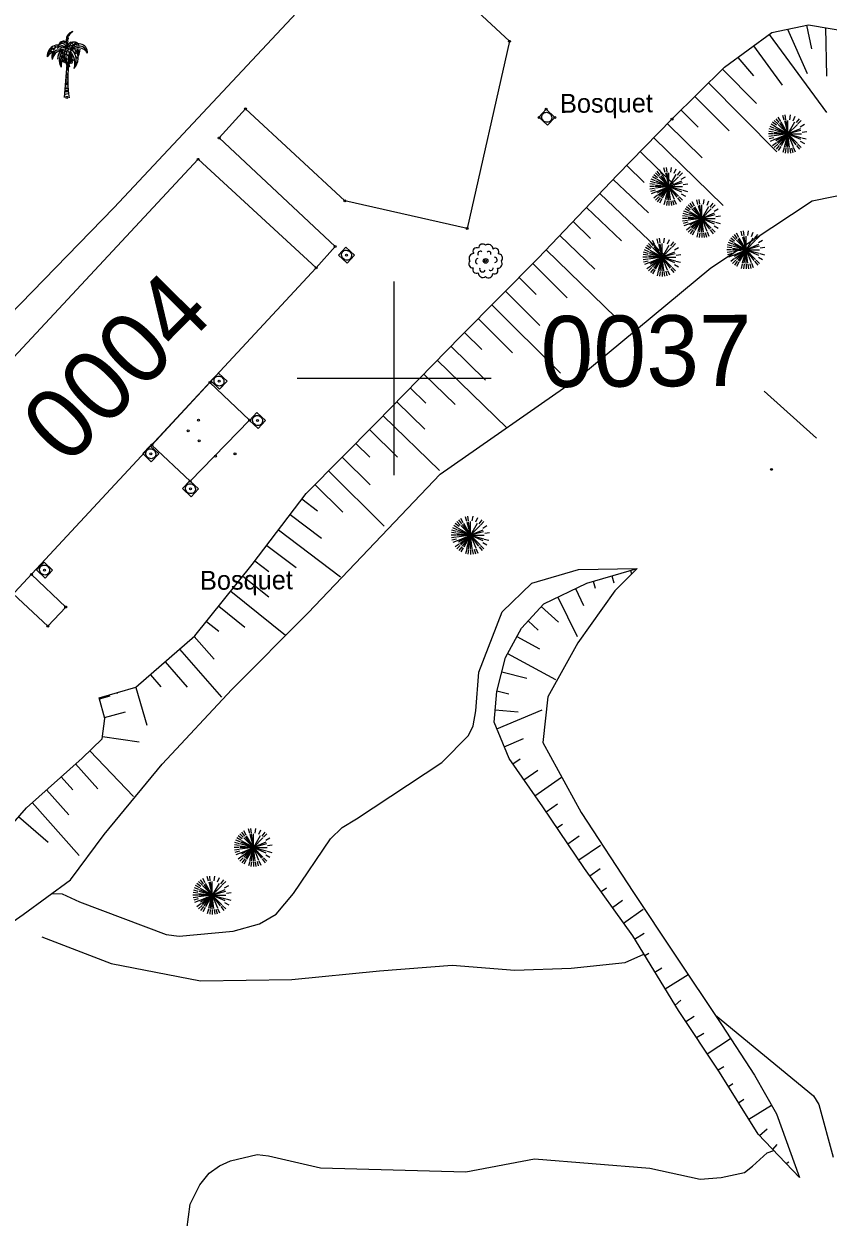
# Model space of a CAD drawing. Extents: x 344013 to 344423, y 298505 to 298795.
# Drawn here: x 344180.9 to 344222.4, y 298556.7 to 298618.3 of the extents above; entities that cross this region are included whole.
import ezdxf

# ---------------------------------------------------------------- set-up
doc = ezdxf.new("R2010")
doc.units = 0
for name, color, linetype in [('Default', 7, 'Continuous'), ('DH_CADRE -CARTOUCHE', 7, 'Continuous'), ('DH_CADRE-CARTOUCHE-NORD', 7, 'Continuous'), ('IMM_VOIRIE VOIE FERREE', 7, 'Continuous'), ('PC_CONCRETE', 7, 'Continuous'), ('PS_BOLT', 7, 'Continuous'), ('PS_CONST', 7, 'Continuous'), ('TOPO_COURBE NIVEAU', 7, 'Continuous'), ('TOPO_POINT', 7, 'Continuous'), ('TOPO_TALUS-TERRAIN NATUREL', 7, 'Continuous'), ('VOIRIE_ESPACE VERT', 7, 'Continuous')]:
    doc.layers.add(name, color=color, linetype=linetype)

# ---------------------------------------------------------------- blocks, each defined once
blk = doc.blocks.new('REG_INC')
at = {"layer": 'Default'}
for p, q in [((0, 1), (1, 1)), ((0, 0), (0, 1)), ((1, 0), (0, 0)), ((1, 1), (1, 0))]:
    blk.add_line(p, q, dxfattribs=at)
for start, end in [(135.0055, 180.0055), (180.0066, 225.0066), (90.0058, 135.0058), (225.0069, 270.0069), (45.0069, 90.0069), (270.0058, 315.0058), (0.0066, 45.0066), (315.0055, 0.0055)]:
    blk.add_arc((0.5, 0.5), 0.44, start, end, dxfattribs=at)
blk = doc.blocks.new('POINT_DISPLAY')
at = {"layer": 'Default'}
blk.add_circle((0, 0), 0.05, dxfattribs=at)
blk = doc.blocks.new('COCO')
at = {"layer": 'Default'}
for p, q in [((0.047, 0.655), (-0.058, 0.642)), ((-0.046, 0.891), (0.052, 0.927)), ((0.054, 0.998), (-0.041, 0.985)), ((-0.037, 1.06), (0.056, 1.071)), ((0.058, 1.14), (-0.03, 1.162)), ((-0.026, 1.226), (0.061, 1.212)), ((0.046, 0.033), (-0.076, 0.051)), ((-0.073, 0.17), (0.045, 0.209)), ((0.045, 0.292), (-0.07, 0.288)), ((-0.068, 0.371), (0.045, 0.374)), ((0.045, 0.47), (-0.065, 0.453)), ((-0.062, 0.537), (0.046, 0.552))]:
    blk.add_line(p, q, dxfattribs=at)
for points in [[(0.029, 2.551), (-0.016, 2.896), (0.002, 3.125), (0.059, 3.241), (0.173, 3.348), (0.189, 3.356), (0.282, 3.415), (0.266, 3.373), (0.2, 3.318), (0.143, 3.247), (0.093, 3.2), (0.081, 3.165), (0.057, 3.133), (0.057, 3.099), (0.06, 3.037), (0.039, 2.989), (0.039, 2.944), (0.049, 2.877), (0.037, 2.841), (0.013, 2.736)], [(-0.746, 2.559), (-0.864, 2.483)], [(-0.607, 2.534), (-0.704, 2.443)], [(-0.636, 2.639), (-0.541, 2.608)], [(-0.421, 2.58), (-0.503, 2.523)], [(-0.487, 2.68), (-0.386, 2.65)], [(-0.183, 2.493), (-0.348, 2.417), (-0.401, 2.307), (-0.448, 2.203), (-0.471, 2.086), (-0.474, 2.023), (-0.466, 1.973), (-0.455, 2.054), (-0.451, 2.146), (-0.387, 2.292), (-0.351, 2.354), (-0.284, 2.404), (-0.233, 2.445), (-0.012, 2.495)], [(-0.256, 2.553), (-0.385, 2.508)], [(0.013, 2.736), (0.036, 2.813), (0.046, 2.746)], [(0.133, 2.608), (0.185, 2.634)], [(0.196, 2.687), (0.323, 2.715)], [(0.283, 2.765), (0.331, 2.786)], [(-0.77, 2.413), (-0.836, 2.333)], [(-0.321, 1.997), (-0.364, 1.9)], [(-0.276, 2.151), (-0.329, 2.086)], [(-0.203, 2.314), (-0.274, 2.258)], [(-0.23, 2.152), (-0.237, 2.043)], [(-0.161, 2.218), (-0.158, 2.122)], [(-0.059, 2.024), (-0.083, 1.998)], [(-0.04, 2.247), (-0.081, 2.179)], [(0.015, 2.414), (-0.056, 2.352)], [(-0.025, 2.032), (0.002, 1.954)], [(0.022, 2.24), (0.043, 2.13)], [(0.081, 2.404), (0.106, 2.299)], [(0.385, 2.37), (0.469, 2.254)], [(0.473, 2.115), (0.509, 2.012)], [(-0.055, 0.716), (0.048, 0.717), (0.049, 0.787), (-0.051, 0.795)]]:
    blk.add_lwpolyline(points, dxfattribs=at)
for centre, radius in [((-0.187, 1.897), 0.0384), ((-0.144, 1.978), 0.0616), ((-0.124, 1.896), 0.0376), ((-0.11, 1.84), 0.0471), ((0.134, 1.862), 0.0549), ((0.208, 1.822), 0.0626), ((0.254, 1.938), 0.0628)]:
    blk.add_circle(centre, radius, dxfattribs=at)
for centre, radius, start, end in [((-0.427, 2.113), 0.595, 43.61211, 181.46245), ((-0.38, 1.964), 0.648, 57.91917, 166.62012), ((-0.123, 2.59), 0.323, 122.34745, 158.76357), ((-0.199, 2.618), 0.238, 4.52184, 154.10099), ((-0.252, 2.556), 0.231, 4.24411, 134.21032), ((-0.16, 2.647), 0.255, 21.08609, 122.34745), ((0.62, 2.159), 0.753, 153.08677, 230.11243), ((0.659, 2.068), 0.718, 142.35537, 222.27942), ((-0.007, 2.465), 0.0563, 81.74752, 144.30354), ((-0.189, 1.21), 1.324, 71.37146, 81.74752), ((0.376, 2.508), 0.372, 113.76809, 175.33093), ((0.376, 2.508), 0.372, 113.76809, 175.33093), ((0.294, 2.595), 0.256, 198.67654, 199.76266), ((0.963, 1.939), 0.9, 143.98655, 203.42885), ((0.418, 2.527), 0.326, 97.12484, 183.95116), ((1.025, 2.053), 0.958, 126.68582, 153.16638), ((0.59, 2.015), 0.548, 29.56544, 139.35171), ((-0.341, 1.9), 0.828, 46.97669, 50.12313), ((0.618, 2.316), 0.451, 356.16265, 159.00089), ((0.609, 2.187), 0.468, 12.10772, 148.31459), ((0.344, 2.407), 0.451, 69.08173, 104.86204), ((-0.157, 2.027), 0.74, 51.24751, 54.5217), ((-1.005, 1.577), 1.786, 37.56679, 40.51564), ((-0.157, 2.027), 0.74, 315.14717, 39.02392), ((-0.254, 2.28), 0.869, 28.47252, 37.09653), ((0.493, 2.767), 0.0679, 35.32051, 126.68582), ((-1.704, 1.849), 2.327, 7.59784, 16.36658), ((-0.054, 2.379), 0.738, 25.81944, 35.32051), ((-0.254, 2.28), 0.869, 350.88829, 14.70633), ((-0.482, 2.552), 1.161, 339.35966, 356.59253), ((-0.291, 1.543), 0.918, 76.73894, 142.80251), ((-0.3, 2.12), 0.482, 151.13313, 199.59422), ((-0.196, 1.874), 0.565, 78.51401, 171.35044), ((-0.32, 2.055), 0.433, 119.08336, 188.76207), ((0.362, 1.922), 0.754, 136.71129, 208.82208), ((0.551, 1.79), 0.879, 137.73301, 194.37159), ((0.649, 1.599), 0.949, 145.51456, 182.45279), ((0.544, 1.816), 0.474, 137.19533, 172.89867), ((0.308, 2.014), 0.226, 121.42967, 182.28997), ((27.302, 0.106), 27.266, 175.47911, 176.55971), ((0.311, 2.152), 0.219, 141.85595, 191.51747), ((0.372, 1.847), 0.277, 133.59561, 173.48701), ((0.808, 1.542), 0.777, 142.23578, 156.28002), ((0.242, 1.964), 0.147, 110.97274, 165.97557), ((0.404, 1.878), 0.354, 125.05854, 146.38926), ((0.398, 2.098), 0.301, 136.45687, 162.06855), ((0.357, 2.084), 0.244, 133.11836, 172.75341), ((-0.759, 1.958), 0.922, 344.85055, 15.89877), ((-0.404, 2.045), 0.619, 329.46655, 26.67931), ((-0.289, 2.11), 0.564, 317.8279, 12.33856), ((-0.543, 1.744), 0.96, 344.8781, 41.14605), ((-0.341, 1.9), 0.828, 334.06866, 41.194), ((-85.428, 7.294), 85.622, 355.11326, 356.26352), ((-0.279, 1.637), 0.281, 2.14987, 36.63246), ((-0.265, 1.505), 0.316, 339.99973, 25.72283), ((0.199, 1.66), 0.176, 166.9443, 185.59662)]:
    blk.add_arc(centre, radius, start, end, dxfattribs=at)
blk.add_ellipse((27.425, 0.272), major_axis=(-27.371, 0.966), ratio=0.529859, start_param=6.255729, end_param=6.369141, dxfattribs=at)
blk = doc.blocks.new('ARB1')
at = {"layer": 'Default'}
blk.add_circle((0, 0), 0.122, dxfattribs=at)
for centre, radius, start, end in [((-0.471, 0.503), 0.183, 53.95544, 222.20655), ((-0.153, 0.664), 0.211, 43.69255, 183.5969), ((0.139, 0.613), 0.241, 358.45835, 125.19284), ((0.501, 0.468), 0.183, 325.14445, 131.01755), ((-0.613, 0.139), 0.241, 88.45835, 215.19284), ((-0.373, -0.024), 0.149, 103.70924, 242.34652), ((-0.276, 0.37), 0.134, 52.43963, 209.54959), ((0.164, 0.38), 0.112, 330.58954, 133.71274), ((0.458, 0.052), 0.137, 276.62143, 88.96702), ((0.613, -0.139), 0.241, 268.45835, 35.19284), ((0.664, 0.153), 0.211, 313.69255, 93.5969), ((-0.664, -0.153), 0.211, 133.69255, 273.5969), ((-0.478, -0.443), 0.19, 155.22426, 300.93774), ((-0.139, -0.613), 0.241, 178.45835, 305.19284), ((-0.163, -0.42), 0.148, 159.53711, 338.16632), ((0.271, -0.38), 0.112, 210.58954, 13.71274), ((0.448, -0.483), 0.188, 243.13234, 33.02965), ((0.153, -0.664), 0.211, 223.69255, 3.5969)]:
    blk.add_arc(centre, radius, start, end, dxfattribs=at)
blk = doc.blocks.new('ARB2')
at = {"layer": 'Default'}
for p, q in [((-0.513, 0.525), (-0.688, 0.702)), ((-0.438, 0.589), (-0.588, 0.786)), ((-0.356, 0.642), (-0.481, 0.858)), ((-0.181, 0.716), (-0.244, 0.956)), ((-0.088, 0.736), (-0.119, 0.983)), ((0.106, 0.736), (0.144, 0.983)), ((0.287, 0.684), (0.388, 0.914)), ((0.456, 0.589), (0.612, 0.786)), ((0.531, 0.525), (0.706, 0.702)), ((-0.731, 0), (-0.981, 0)), ((-0.725, 0.1), (-0.969, 0.133)), ((-0.706, 0.195), (-0.944, 0.259)), ((-0.675, 0.286), (-0.9, 0.381)), ((-0.631, 0.373), (-0.844, 0.497)), ((-0.575, 0.453), (-0.775, 0.605)), ((0.65, 0.373), (0.862, 0.497)), ((0.744, 0.1), (0.987, 0.133)), ((-0.725, -0.1), (-0.969, -0.133)), ((-0.706, -0.195), (-0.944, -0.259)), ((-0.675, -0.287), (-0.9, -0.383)), ((-0.575, -0.455), (-0.775, -0.605)), ((-0.513, -0.527), (-0.688, -0.702)), ((-0.438, -0.591), (-0.588, -0.787)), ((0.456, -0.591), (0.612, -0.787)), ((0.531, -0.527), (0.706, -0.702)), ((0.65, -0.373), (0.862, -0.498)), ((0.725, -0.195), (0.963, -0.259)), ((-0.356, -0.644), (-0.481, -0.859)), ((-0.181, -0.717), (-0.244, -0.956)), ((-0.088, -0.737), (-0.119, -0.983)), ((0.013, -0.741), (0.013, -0.989)), ((0.106, -0.737), (0.144, -0.983)), ((0.2, -0.717), (0.263, -0.956)), ((0.287, -0.686), (0.388, -0.916))]:
    blk.add_line(p, q, dxfattribs=at)
for points in [[(-0.169, 0.677), (0.013, 0), (-0.6, 0.35)], [(0.013, 0.008), (0.013, 0), (-0.081, 0.695)], [(0.362, 0.608), (0.013, 0), (0.013, 0.702)], [(-0.487, -0.497), (0.013, 0), (-0.694, 0)], [(-0.688, 0.091), (0.013, 0), (-0.338, 0.608)], [(-0.638, -0.269), (0.013, 0), (-0.688, -0.092)], [(-0.487, 0.495), (0.013, 0), (-0.669, 0.181)], [(-0.419, 0.556), (0.013, 0), (-0.638, 0.269)], [(-0.169, -0.678), (0.013, 0), (-0.6, -0.352)], [(-0.544, -0.428), (0.013, 0), (-0.338, -0.608)], [(-0.081, -0.695), (0.013, 0), (-0.419, -0.558)], [(0.013, -0.702), (0.013, 0), (0, 0)], [(0.656, 0.269), (0.013, 0), (0.506, 0.495)], [(0.688, 0.181), (0.013, 0), (0.713, 0)], [(0.438, -0.558), (0.013, 0), (0.656, -0.269)], [(0.506, -0.497), (0.013, 0), (0.688, -0.181)], [(0.1, -0.695), (0.013, 0), (0.281, -0.648)], [(0.019, 0), (0.013, 0), (0.013, -0.009)]]:
    blk.add_lwpolyline(points, dxfattribs=at)

msp = doc.modelspace()

# ---------------------------------------------------------------- linework, layer by layer
at = {"layer": 'DH_CADRE -CARTOUCHE'}
msp.add_lwpolyline([(344173.637, 298593.851), (344189.896, 298611.294), (344195.985, 298605.701), (344179.76, 298588.225)], close=True, dxfattribs=at)
at = {"layer": 'DH_CADRE-CARTOUCHE-NORD'}
for p, q in [((344200, 298595), (344200, 298605)), ((344195, 298600), (344205, 298600))]:
    msp.add_line(p, q, dxfattribs=at)
at = {"layer": 'IMM_VOIRIE VOIE FERREE'}
msp.add_line((344221.778, 298596.916), (344219.076, 298599.34), dxfattribs=at)
at = {"layer": 'PS_BOLT'}
for points in [[(344173.637, 298593.851), (344172.292, 298595.161), (344185.567, 298608.8), (344198.259, 298622.397), (344163.217, 298655.561), (344163.898, 298656.291), (344171.693, 298664.218), (344209.192, 298629.258), (344201.744, 298621.299), (344205.95, 298617.379), (344203.771, 298607.721), (344197.46, 298609.156), (344192.341, 298613.899), (344190.988, 298612.393), (344196.963, 298606.8), (344195.985, 298605.701)], [(344181.304, 298589.888), (344183.07, 298588.205), (344182.156, 298587.216), (344180.365, 298588.877)]]:
    msp.add_lwpolyline(points, dxfattribs=at)
msp.add_lwpolyline([(344187.514, 298596.559), (344189.49, 298594.691), (344192.553, 298597.847), (344190.509, 298599.787)], close=True, dxfattribs=at)
at = {"layer": 'TOPO_COURBE NIVEAU'}
for points in [[(344182.365, 298573.436), (344182.886, 298573.416), (344183.782, 298573.006), (344188.242, 298571.307), (344188.925, 298571.234), (344191.696, 298571.482), (344193.065, 298571.873), (344193.915, 298572.359), (344194.821, 298573.435), (344196.721, 298576.256), (344197.328, 298576.829), (344198.067, 298577.284), (344202.461, 298580.187), (344203.841, 298581.577), (344204.07, 298582.072), (344204.22, 298582.851), (344204.366, 298584.836), (344205.57, 298587.951), (344207.101, 298589.427), (344209.508, 298590.137), (344212.523, 298590.19)], [(344189.312, 298556.099), (344189.48, 298557.412), (344189.986, 298558.403), (344190.474, 298559), (344191.003, 298559.385), (344191.569, 298559.636), (344192.937, 298559.964), (344193.528, 298559.892), (344196.21, 298559.282), (344203.689, 298559.074), (344207.24, 298559.752), (344213.187, 298559.27), (344215.782, 298558.7), (344216.853, 298558.777), (344218.066, 298559.043), (344218.475, 298559.372), (344219.233, 298560.063), (344219.572, 298560.172)]]:
    msp.add_lwpolyline(points, dxfattribs=at)
at = {"layer": 'TOPO_TALUS-TERRAIN NATUREL'}
for p, q in [((344221.257, 298618.208), (344221.511, 298616.983)), ((344222.243, 298618.084), (344222.292, 298615.584)), ((344219.33, 298617.732), (344222.289, 298613.7)), ((344220.278, 298618.006), (344221.294, 298615.721)), ((344218.523, 298617.14), (344220.003, 298615.124)), ((344217.717, 298616.549), (344218.529, 298615.598)), ((344216.924, 298615.941), (344218.685, 298614.164)), ((344216.214, 298615.237), (344219.734, 298611.684)), ((344215.503, 298614.533), (344217.263, 298612.756)), ((344214.793, 298613.828), (344215.68, 298612.948)), ((344214.086, 298613.12), (344215.876, 298611.374)), ((344213.388, 298612.404), (344216.967, 298608.912)), ((344212.689, 298611.689), (344214.479, 298609.942)), ((344211.99, 298610.973), (344212.891, 298610.105)), ((344211.295, 298610.254), (344213.106, 298608.53)), ((344210.605, 298609.53), (344214.228, 298606.081)), ((344209.915, 298608.805), (344211.727, 298607.081)), ((344209.226, 298608.081), (344210.131, 298607.218)), ((344208.536, 298607.356), (344210.347, 298605.632)), ((344207.846, 298606.631), (344211.43, 298603.143)), ((344207.15, 298605.913), (344208.923, 298604.149)), ((344206.445, 298605.204), (344207.331, 298604.322)), ((344205.739, 298604.495), (344207.512, 298602.731)), ((344205.034, 298603.786), (344208.579, 298600.258)), ((344204.328, 298603.077), (344206.1, 298601.313)), ((344203.622, 298602.368), (344204.514, 298601.492)), ((344202.923, 298601.653), (344204.716, 298599.91)), ((344202.226, 298600.936), (344205.813, 298597.45)), ((344201.529, 298600.218), (344203.143, 298598.65)), ((344200.832, 298599.501), (344201.639, 298598.717)), ((344200.135, 298598.784), (344201.587, 298597.372)), ((344199.438, 298598.066), (344202.343, 298595.243)), ((344198.736, 298597.353), (344200.172, 298595.925)), ((344198.031, 298596.644), (344198.749, 298595.93)), ((344197.325, 298595.935), (344198.761, 298594.506)), ((344196.62, 298595.225), (344199.492, 298592.369)), ((344195.915, 298594.516), (344197.351, 298593.088)), ((344195.246, 298593.775), (344196.053, 298593.163)), ((344194.641, 298592.978), (344196.255, 298591.754)), ((344194.036, 298592.182), (344197.23, 298589.758)), ((344193.432, 298591.385), (344194.948, 298590.234)), ((344192.827, 298590.588), (344193.547, 298590.042)), ((344192.207, 298589.803), (344193.547, 298588.73)), ((344211.229, 298589.814), (344211.333, 298589.455)), ((344212.189, 298590.093), (344212.239, 298589.92)), ((344209.347, 298589.153), (344209.766, 298588.282)), ((344210.268, 298589.535), (344210.372, 298589.178)), ((344191.581, 298589.023), (344194.408, 298586.757)), ((344208.446, 298588.719), (344209.43, 298586.677)), ((344190.956, 298588.242), (344192.298, 298587.166)), ((344207.586, 298588.229), (344208.468, 298587.421)), ((344190.33, 298587.462), (344190.967, 298586.951)), ((344206.911, 298587.491), (344207.428, 298587.017)), ((344189.698, 298586.687), (344190.718, 298585.518)), ((344206.332, 298586.684), (344207.5, 298586.046)), ((344188.945, 298586.029), (344191.098, 298583.562)), ((344205.852, 298585.806), (344208.318, 298584.459)), ((344188.191, 298585.372), (344189.327, 298584.07)), ((344205.548, 298584.859), (344206.84, 298584.527)), ((344187.437, 298584.714), (344187.977, 298584.096)), ((344184.813, 298583.473), (344185.367, 298583.624)), ((344185.721, 298583.781), (344185.731, 298583.748)), ((344186.682, 298584.06), (344187.246, 298582.115)), ((344205.299, 298583.89), (344205.913, 298583.733)), ((344185.076, 298582.508), (344186.155, 298582.803)), ((344205.205, 298582.895), (344206.403, 298582.792)), ((344205.289, 298581.925), (344207.633, 298582.9)), ((344184.964, 298581.519), (344186.858, 298581.259)), ((344205.672, 298581.001), (344206.675, 298581.418)), ((344184.311, 298580.792), (344186.563, 298578.425)), ((344183.576, 298580.114), (344184.724, 298578.827)), ((344206.12, 298580.113), (344206.501, 298580.377)), ((344182.83, 298579.447), (344183.436, 298578.769)), ((344206.691, 298579.291), (344207.414, 298579.794)), ((344207.262, 298578.47), (344208.635, 298579.425)), ((344182.084, 298578.781), (344183.234, 298577.493)), ((344181.337, 298578.115), (344183.765, 298575.395)), ((344207.83, 298577.647), (344208.421, 298578.049)), ((344180.646, 298577.395), (344182.159, 298576.077)), ((344208.392, 298576.819), (344208.673, 298577.01)), ((344208.955, 298575.992), (344209.547, 298576.395)), ((344209.517, 298575.165), (344210.642, 298575.93)), ((344210.088, 298574.344), (344210.614, 298574.719)), ((344210.668, 298573.529), (344210.946, 298573.727)), ((344211.249, 298572.715), (344211.776, 298573.09)), ((344211.829, 298571.9), (344212.831, 298572.614)), ((344212.399, 298571.078), (344212.897, 298571.383)), ((344212.922, 298570.225), (344213.135, 298570.356)), ((344213.445, 298569.373), (344213.808, 298569.596)), ((344213.968, 298568.52), (344215.152, 298569.246)), ((344214.491, 298567.667), (344214.783, 298567.93)), ((344215.034, 298566.828), (344215.46, 298567.096)), ((344215.588, 298565.995), (344215.964, 298566.231)), ((344216.142, 298565.162), (344217.337, 298565.957)), ((344216.696, 298564.329), (344216.994, 298564.514)), ((344217.229, 298563.483), (344217.453, 298563.634)), ((344217.758, 298562.634), (344218.026, 298562.825)), ((344218.287, 298561.785), (344219.451, 298562.51)), ((344218.831, 298560.948), (344219.232, 298561.288)), ((344219.522, 298560.225), (344219.745, 298560.486)), ((344220.213, 298559.501), (344220.352, 298559.598))]:
    msp.add_line(p, q, dxfattribs=at)
for points in [[(344163.934, 298561.868), (344165.849, 298564.688), (344168.923, 298567.814), (344171.996, 298570.469), (344176.091, 298573.09), (344178.872, 298575.358), (344181.046, 298577.856), (344183.915, 298580.416), (344184.947, 298581.398), (344185.091, 298582.452), (344184.802, 298583.514), (344186.691, 298584.063), (344189.735, 298586.719), (344192.676, 298590.389), (344195.465, 298594.065), (344199.099, 298597.718), (344203.435, 298602.18), (344207.43, 298606.195), (344211.519, 298610.49), (344214.324, 298613.364), (344217.026, 298616.042), (344219.477, 298617.84), (344221.365, 298618.23), (344223.701, 298617.841)], [(344163.934, 298561.868), (344170.201, 298566.564), (344176.522, 298569.299), (344180.879, 298572.338), (344183.313, 298574.136), (344185.048, 298576.477), (344188.051, 298580.099), (344191.638, 298583.956), (344195.571, 298587.909), (344198.338, 298590.807), (344202.379, 298595.055), (344209.468, 298599.999), (344216.32, 298605.698), (344221.544, 298609.146), (344226.03, 298610.067), (344230.196, 298608.376), (344234.376, 298605.349), (344238.337, 298601.801), (344242.051, 298598.625), (344245.256, 298595.883), (344247.329, 298593.914), (344248.413, 298593.093)], [(344220.903, 298558.778), (344218.768, 298561.014), (344216.773, 298564.213), (344214.662, 298567.387), (344212.3, 298571.239), (344209.819, 298574.721), (344207.66, 298577.896), (344205.926, 298580.392), (344205.15, 298582.259), (344205.287, 298583.842), (344205.737, 298585.596), (344206.567, 298587.115), (344207.71, 298588.364), (344209.939, 298589.439), (344212.523, 298590.19)], [(344212.523, 298590.19), (344211.38, 298589.036), (344209.463, 298586.355), (344207.924, 298583.579), (344207.66, 298581.209), (344209.646, 298577.609), (344212.346, 298573.48), (344214.45, 298570.298), (344216.869, 298566.673), (344218.573, 298564.064), (344219.703, 298562.064), (344220.903, 298558.778)], [(344181.841, 298571.197), (344185.408, 298569.821), (344190.018, 298568.927), (344194.735, 298568.986), (344199.253, 298569.445), (344202.999, 298569.73), (344206.218, 298569.472), (344209.131, 298569.584), (344211.917, 298569.869), (344212.879, 298570.296)], [(344216.544, 298567.159), (344216.561, 298567.158), (344221.613, 298563.003), (344221.888, 298562.539), (344222.63, 298559.823)]]:
    msp.add_lwpolyline(points, dxfattribs=at)

# ---------------------------------------------------------------- block references
at = {"layer": 'PC_CONCRETE', "xscale": 0.607622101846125, "yscale": -0.5584542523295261, "rotation": -43.338150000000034}
for p in [(344207.841, 298613.874), (344197.519, 298606.76), (344190.944, 298600.269), (344192.932, 298598.234), (344187.425, 298596.522), (344189.473, 298594.718), (344181.953, 298590.522)]:
    msp.add_blockref('REG_INC', p, dxfattribs=at)
at = {"layer": 'TOPO_POINT'}
for p in [(344205.95, 298617.379), (344183.131, 298614.483), (344192.341, 298613.899), (344207.841, 298613.874), (344207.47, 298613.456), (344208.283, 298613.457), (344214.324, 298613.364), (344220.285, 298612.601), (344190.988, 298612.393), (344189.896, 298611.294), (344214.155, 298609.894), (344197.46, 298609.156), (344215.842, 298608.242), (344203.771, 298607.721), (344196.963, 298606.8), (344197.549, 298606.349), (344218.129, 298606.626), (344195.985, 298605.701), (344204.718, 298606.052), (344213.801, 298606.244), (344190.509, 298599.787), (344190.975, 298599.858), (344189.916, 298597.839), (344192.553, 298597.847), (344192.962, 298597.823), (344189.386, 298597.285), (344187.514, 298596.559), (344189.95, 298596.774), (344187.455, 298596.11), (344190.79, 298595.98), (344191.798, 298596.099), (344219.453, 298595.304), (344189.49, 298594.691), (344189.503, 298594.306), (344203.924, 298591.906), (344181.304, 298589.888), (344181.983, 298590.111), (344183.07, 298588.205), (344182.156, 298587.216), (344192.735, 298575.804), (344190.613, 298573.343)]:
    msp.add_blockref('POINT_DISPLAY', p, dxfattribs=at)
at = {"layer": 'VOIRIE_ESPACE VERT'}
for name, p in [('COCO', (344183.131, 298614.483)), ('ARB2', (344220.285, 298612.601)), ('ARB2', (344214.155, 298609.894)), ('ARB2', (344215.842, 298608.242)), ('ARB2', (344218.129, 298606.626)), ('ARB2', (344213.801, 298606.244)), ('ARB1', (344204.718, 298606.052)), ('ARB2', (344203.924, 298591.906)), ('ARB2', (344192.735, 298575.804)), ('ARB2', (344190.613, 298573.343))]:
    msp.add_blockref(name, p, dxfattribs=at)

# ---------------------------------------------------------------- texts
at = {"layer": 'PS_CONST'}
for s, height, rotation, p in [('Bosquet', 0.9758, 0.36651, (344208.554, 298613.689)), ('0004', 3.662, 45.36652, (344183.129, 298595.424)), ('0037', 3.662, 0.36652, (344207.556, 298599.547)), ('Bosquet', 0.9758, 0.36652, (344189.996, 298589.09))]:
    msp.add_text(s, height=height, rotation=rotation, dxfattribs=at).set_placement(p)

doc.saveas('drawing.dxf')
